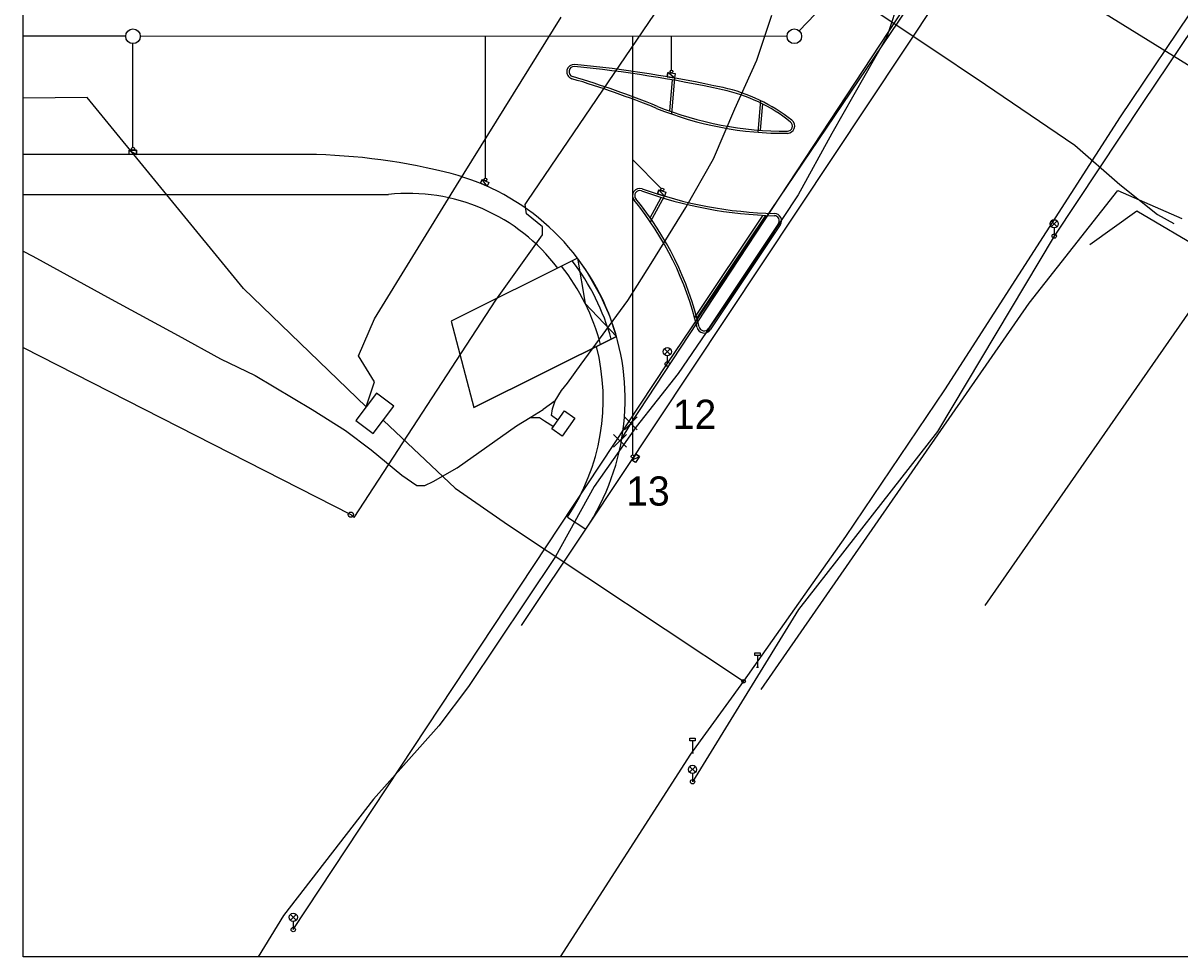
# Model space of a CAD drawing. Extents: x -263861 to -263441, y -1242367 to -1242070.
# Drawn here: x -263861.4 to -263782.2, y -1242367.2 to -1242303.2 of the extents above; entities that cross this region are included whole.
import ezdxf

# ---------------------------------------------------------------- set-up
doc = ezdxf.new("R2010")
doc.units = 0
for name, color, linetype in [('KFA_BODY', 7, 'Continuous'), ('KFA_JESTV_IS_DSP', 7, 'Continuous'), ('KFA_SITUACIA_DSP', 7, 'Continuous'), ('KFA_VO_prelozka_pri_vjazde_do KFA_TRASA', 7, 'Continuous'), ('RAM_NA_TLAC_A3_1-1000', 7, 'Continuous')]:
    doc.layers.add(name, color=color, linetype=linetype)

msp = doc.modelspace()

# ---------------------------------------------------------------- linework, layer by layer
at = {"layer": 'KFA_BODY'}
for p, q in [((-263820.235, -1242331.097), (-263819.351, -1242330.213)), ((-263819.351, -1242331.097), (-263820.235, -1242330.213)), ((-263819.793, -1242330.655), (-263819.793, -1242330.655)), ((-263820.978, -1242332.301), (-263820.094, -1242331.417)), ((-263820.094, -1242332.301), (-263820.978, -1242331.417)), ((-263820.536, -1242331.859), (-263820.536, -1242331.859))]:
    msp.add_line(p, q, dxfattribs=at)
at = {"layer": 'KFA_JESTV_IS_DSP'}
for p, q in [((-263771.766, -1242288.099), (-263786.259, -1242309.662)), ((-263817.295, -1242326.595), (-263792.966, -1242290.553)), ((-263806.91, -1242290.428), (-263775.785, -1242309.71)), ((-263775.662, -1242295.19), (-263784.703, -1242308.688)), ((-263826.85, -1242315.4), (-263815.315, -1242298.423)), ((-263809.14, -1242298.34), (-263799.44, -1242304.8)), ((-263801.33, -1242301.36), (-263802.26, -1242304.18)), ((-263831.753, -1242314.378), (-263824.576, -1242302.847)), ((-263811.16, -1242305.78), (-263810.13, -1242302.69)), ((-263802.26, -1242304.18), (-263806.02, -1242310.8)), ((-263799.44, -1242304.8), (-263795.49, -1242307.45)), ((-263812.66, -1242309.11), (-263811.16, -1242305.78)), ((-263795.49, -1242307.45), (-263789.36, -1242311.61)), ((-263857.064, -1242308.341), (-263861.443, -1242308.381)), ((-263846.335, -1242321.415), (-263857.064, -1242308.341)), ((-263814.12, -1242312.54), (-263812.66, -1242309.11)), ((-263784.703, -1242308.688), (-263790.778, -1242317.834)), ((-263786.259, -1242309.662), (-263798.305, -1242328.357)), ((-263806.02, -1242310.8), (-263808.33, -1242315.01)), ((-263789.36, -1242311.61), (-263786.29, -1242314.3)), ((-263816.02, -1242315.88), (-263814.12, -1242312.54)), ((-263837.368, -1242323.507), (-263831.753, -1242314.378)), ((-263792.5, -1242322.419), (-263786.416, -1242314.718)), ((-263786.416, -1242314.718), (-263782.039, -1242316.62)), ((-263786.29, -1242314.3), (-263783.7, -1242316.36)), ((-263827.03, -1242315.679), (-263826.85, -1242315.4)), ((-263827.03, -1242315.679), (-263826.85, -1242315.4)), ((-263808.33, -1242315.01), (-263812.71, -1242321.64)), ((-263826.939, -1242316.313), (-263827.03, -1242315.679)), ((-263826.939, -1242316.313), (-263827.03, -1242315.679)), ((-263825.841, -1242317.203), (-263826.939, -1242316.313)), ((-263825.841, -1242317.203), (-263826.939, -1242316.313)), ((-263818.4, -1242319.72), (-263816.02, -1242315.88)), ((-263788.344, -1242318.406), (-263785.115, -1242316.112)), ((-263785.115, -1242316.112), (-263778.688, -1242319.903)), ((-263783.7, -1242316.36), (-263782.58, -1242316.96)), ((-263790.977, -1242316.792), (-263790.579, -1242317.189)), ((-263790.579, -1242316.792), (-263790.977, -1242317.189)), ((-263829.05, -1242322.225), (-263825.851, -1242317.746)), ((-263825.851, -1242317.746), (-263825.841, -1242317.203)), ((-263825.851, -1242317.746), (-263825.841, -1242317.203)), ((-263790.778, -1242317.834), (-263798.769, -1242331.222)), ((-263790.778, -1242317.272), (-263790.778, -1242317.834)), ((-263861.443, -1242318.877), (-263860.78, -1242319.2)), ((-263860.78, -1242319.2), (-263855.41, -1242322.16)), ((-263778.588, -1242318.789), (-263795.542, -1242343.129)), ((-263820, -1242322.24), (-263818.4, -1242319.72)), ((-263837.937, -1242329.538), (-263846.335, -1242321.415)), ((-263812.71, -1242321.64), (-263816.56, -1242327.25)), ((-263855.41, -1242322.16), (-263850.82, -1242324.64)), ((-263838.758, -1242337.112), (-263829.05, -1242322.225)), ((-263823.2, -1242326.6), (-263820, -1242322.24)), ((-263810.862, -1242348.9), (-263792.5, -1242322.419)), ((-263838.469, -1242326.041), (-263837.368, -1242323.507)), ((-263850.82, -1242324.64), (-263847.92, -1242326.23)), ((-263861.443, -1242325.454), (-263838.982, -1242336.914)), ((-263817.494, -1242325.552), (-263817.096, -1242325.95)), ((-263817.096, -1242325.552), (-263817.494, -1242325.95)), ((-263847.92, -1242326.23), (-263845.54, -1242327.38)), ((-263842.931, -1242365.337), (-263817.295, -1242326.595)), ((-263837.363, -1242327.807), (-263838.469, -1242326.041)), ((-263824.13, -1242327.9), (-263823.2, -1242326.6)), ((-263817.295, -1242326.032), (-263817.295, -1242326.595)), ((-263845.54, -1242327.38), (-263841.63, -1242329.71)), ((-263816.56, -1242327.25), (-263819.43, -1242330.89)), ((-263837.937, -1242329.538), (-263837.363, -1242327.807)), ((-263824.55, -1242328.41), (-263824.13, -1242327.9)), ((-263837.233, -1242328.584), (-263838.648, -1242330.455)), ((-263836.032, -1242329.492), (-263837.233, -1242328.584)), ((-263824.97, -1242329.12), (-263824.55, -1242328.41)), ((-263798.305, -1242328.357), (-263805.079, -1242338.406)), ((-263841.63, -1242329.71), (-263839.35, -1242331.16)), ((-263837.446, -1242331.363), (-263836.032, -1242329.492)), ((-263826.7, -1242330.27), (-263825.81, -1242329.72)), ((-263824.97, -1242329.12), (-263825.81, -1242329.72)), ((-263825.23, -1242330.13), (-263825.17, -1242329.67)), ((-263825.21, -1242331.04), (-263824.35, -1242329.81)), ((-263825.17, -1242329.67), (-263824.97, -1242329.12)), ((-263824.35, -1242329.81), (-263823.64, -1242330.31)), ((-263838.648, -1242330.455), (-263837.446, -1242331.363)), ((-263836.754, -1242330.457), (-263831.833, -1242335.111)), ((-263827.64, -1242330.84), (-263826.7, -1242330.27)), ((-263826.7, -1242330.27), (-263826.06, -1242330.26)), ((-263826.06, -1242330.26), (-263825.71, -1242330.48)), ((-263825.71, -1242330.48), (-263825.1, -1242330.88)), ((-263824.79, -1242330.44), (-263825.23, -1242330.13)), ((-263823.64, -1242330.31), (-263824.5, -1242331.54)), ((-263839.35, -1242331.16), (-263837.6, -1242332.48)), ((-263831.7, -1242333.71), (-263827.64, -1242330.84)), ((-263824.5, -1242331.54), (-263825.21, -1242331.04)), ((-263819.43, -1242330.89), (-263822.31, -1242334.98)), ((-263798.769, -1242331.222), (-263808.3, -1242343.414)), ((-263837.6, -1242332.48), (-263835.49, -1242334.21)), ((-263833.34, -1242334.64), (-263831.7, -1242333.71)), ((-263835.49, -1242334.21), (-263834.45, -1242334.91)), ((-263833.91, -1242334.91), (-263833.34, -1242334.64)), ((-263834.45, -1242334.91), (-263833.91, -1242334.91)), ((-263831.833, -1242335.111), (-263828.189, -1242337.632)), ((-263822.31, -1242334.98), (-263824.95, -1242339.77)), ((-263838.982, -1242336.914), (-263838.758, -1242337.112)), ((-263828.189, -1242337.632), (-263812.07, -1242348.322)), ((-263805.079, -1242338.406), (-263812.07, -1242348.322)), ((-263824.95, -1242339.77), (-263830.93, -1242348.68)), ((-263808.3, -1242343.414), (-263815.565, -1242355.209)), ((-263811.305, -1242346.372), (-263810.93, -1242346.372)), ((-263811.305, -1242346.559), (-263811.305, -1242346.372)), ((-263810.93, -1242346.372), (-263810.93, -1242346.559)), ((-263810.93, -1242346.559), (-263811.305, -1242346.559)), ((-263811.118, -1242346.559), (-263811.118, -1242347.372)), ((-263811.18, -1242347.372), (-263811.055, -1242347.372)), ((-263830.93, -1242348.68), (-263832.95, -1242351.39)), ((-263812.07, -1242348.322), (-263815.715, -1242353.33)), ((-263832.95, -1242351.39), (-263837.44, -1242356.4)), ((-263815.76, -1242352.23), (-263815.385, -1242352.23)), ((-263815.76, -1242352.417), (-263815.76, -1242352.23)), ((-263815.385, -1242352.417), (-263815.76, -1242352.417)), ((-263815.572, -1242352.417), (-263815.572, -1242353.23)), ((-263815.385, -1242352.23), (-263815.385, -1242352.417)), ((-263815.715, -1242353.33), (-263824.645, -1242367.205)), ((-263815.635, -1242353.23), (-263815.51, -1242353.23)), ((-263815.764, -1242354.167), (-263815.366, -1242354.564)), ((-263815.366, -1242354.167), (-263815.764, -1242354.564)), ((-263815.565, -1242354.647), (-263815.565, -1242355.209)), ((-263837.44, -1242356.4), (-263843.59, -1242364.38)), ((-263843.59, -1242364.38), (-263845.324, -1242367.205)), ((-263843.13, -1242364.295), (-263842.732, -1242364.692)), ((-263842.732, -1242364.295), (-263843.13, -1242364.692)), ((-263842.931, -1242364.775), (-263842.931, -1242365.337))]:
    msp.add_line(p, q, dxfattribs=at)
for centre, radius in [((-263790.778, -1242316.99), 0.281), ((-263790.778, -1242317.834), 0.15), ((-263817.295, -1242325.751), 0.281), ((-263817.295, -1242326.595), 0.15), ((-263838.982, -1242336.914), 0.179), ((-263812.07, -1242348.322), 0.125), ((-263815.565, -1242354.365), 0.281), ((-263815.565, -1242355.209), 0.15), ((-263842.931, -1242364.493), 0.281), ((-263842.931, -1242365.337), 0.15)]:
    msp.add_circle(centre, radius, dxfattribs=at)
at = {"layer": 'KFA_SITUACIA_DSP'}
for p, q in [((-263822.88, -1242337.914), (-263734.49, -1242204.937)), ((-263780.353, -1242274.236), (-263808.248, -1242303.783)), ((-263854.415, -1242304.147), (-263861.443, -1242304.147)), ((-263809.091, -1242304.153), (-263853.415, -1242304.148)), ((-263829.755, -1242313.856), (-263829.755, -1242304.151)), ((-263819.667, -1242332.824), (-263819.667, -1242304.147)), ((-263817.005, -1242306.465), (-263817.005, -1242304.152)), ((-263853.915, -1242311.749), (-263853.915, -1242304.647)), ((-263817.296, -1242306.914), (-263817.252, -1242306.627)), ((-263817.252, -1242306.627), (-263817.296, -1242306.914)), ((-263817.252, -1242306.627), (-263816.757, -1242306.703)), ((-263816.802, -1242306.99), (-263817.252, -1242306.627)), ((-263816.802, -1242306.99), (-263817.252, -1242306.627)), ((-263816.757, -1242306.703), (-263816.802, -1242306.99)), ((-263816.802, -1242306.99), (-263817.296, -1242306.914)), ((-263817.296, -1242306.914), (-263816.802, -1242306.99)), ((-263816.964, -1242307.132), (-263817.145, -1242309.262)), ((-263816.803, -1242307.008), (-263817.012, -1242309.468)), ((-263810.912, -1242308.547), (-263811.097, -1242310.721)), ((-263810.781, -1242308.779), (-263810.935, -1242310.583)), ((-263861.443, -1242312.232), (-263857.327, -1242312.232)), ((-263842.601, -1242312.24), (-263861.443, -1242312.238)), ((-263854.165, -1242311.949), (-263853.665, -1242311.949)), ((-263854.165, -1242312.239), (-263854.165, -1242311.949)), ((-263854.165, -1242311.949), (-263853.665, -1242312.239)), ((-263854.165, -1242311.949), (-263853.665, -1242312.239)), ((-263853.665, -1242311.949), (-263854.165, -1242311.949)), ((-263853.665, -1242312.239), (-263854.165, -1242312.239)), ((-263853.665, -1242311.949), (-263853.665, -1242312.239)), ((-263853.665, -1242312.239), (-263853.665, -1242311.949)), ((-263817.708, -1242314.574), (-263819.667, -1242312.615)), ((-263830.101, -1242314.219), (-263829.983, -1242313.954)), ((-263829.983, -1242313.954), (-263830.101, -1242314.219)), ((-263829.983, -1242313.954), (-263829.527, -1242314.158)), ((-263829.645, -1242314.423), (-263829.983, -1242313.954)), ((-263829.645, -1242314.423), (-263829.983, -1242313.954)), ((-263829.645, -1242314.423), (-263830.101, -1242314.219)), ((-263830.101, -1242314.219), (-263829.645, -1242314.423)), ((-263829.527, -1242314.158), (-263829.645, -1242314.423)), ((-263817.966, -1242314.94), (-263817.874, -1242314.665)), ((-263817.874, -1242314.665), (-263817.966, -1242314.94)), ((-263817.874, -1242314.665), (-263817.4, -1242314.824)), ((-263817.492, -1242315.099), (-263817.874, -1242314.665)), ((-263817.492, -1242315.099), (-263817.874, -1242314.665)), ((-263861.443, -1242314.982), (-263836.403, -1242314.982)), ((-263818.469, -1242316.58), (-263817.711, -1242315.183)), ((-263818.453, -1242316.866), (-263817.491, -1242315.093)), ((-263817.492, -1242315.099), (-263817.966, -1242314.94)), ((-263817.966, -1242314.94), (-263817.492, -1242315.099)), ((-263817.4, -1242314.824), (-263817.492, -1242315.099)), ((-263810.751, -1242316.405), (-263815.43, -1242323.41)), ((-263810.576, -1242316.414), (-263815.268, -1242323.437)), ((-263809.676, -1242316.98), (-263814.48, -1242324.171)), ((-263809.551, -1242317.064), (-263814.356, -1242324.254)), ((-263823.444, -1242319.346), (-263832.112, -1242323.652)), ((-263813.542, -1242320.69), (-263813.542, -1242320.69)), ((-263813.542, -1242320.69), (-263813.542, -1242320.69)), ((-263832.112, -1242323.652), (-263830.544, -1242329.573)), ((-263820.775, -1242324.719), (-263830.544, -1242329.573)), ((-263819.723, -1242333.187), (-263819.444, -1242332.772)), ((-263819.723, -1242333.187), (-263819.203, -1242332.933)), ((-263819.203, -1242332.933), (-263819.482, -1242333.349)), ((-263819.444, -1242332.772), (-263819.203, -1242332.933)), ((-263819.482, -1242333.349), (-263819.723, -1242333.187)), ((-263824.127, -1242337.081), (-263822.88, -1242337.914)), ((-263827.28, -1242344.5), (-263822.88, -1242337.914))]:
    msp.add_line(p, q, dxfattribs=at)
for points in [[(-263832.112, -1242323.652), (-263830.544, -1242329.573), (-263820.775, -1242324.719), (-263821.24, -1242323.31), (-263821.84, -1242321.938), (-263822.869, -1242320.154), (-263823.444, -1242319.346), (-263832.112, -1242323.652)], [(-263823.444, -1242319.346), (-263822.93, -1242322.44), (-263820.775, -1242324.719)]]:
    msp.add_lwpolyline(points, dxfattribs=at)
msp.add_lwpolyline([(-263819.723, -1242333.187), (-263819.203, -1242332.933), (-263819.444, -1242332.772)], close=True, dxfattribs=at)
for centre, radius in [((-263853.915, -1242304.147), 0.5), ((-263808.591, -1242304.147), 0.5), ((-263817.005, -1242306.565), 0.1), ((-263853.915, -1242311.849), 0.1), ((-263829.755, -1242313.956), 0.1), ((-263817.637, -1242314.644), 0.1), ((-263819.667, -1242332.924), 0.1)]:
    msp.add_circle(centre, radius, dxfattribs=at)
for centre, radius, start, end in [((-263823.686, -1242306.574), 0.5, 84.50312, 253.37264), ((-263832, -1242392.966), 87.291, 77.74517, 84.50312), ((-263823.686, -1242306.574), 0.35, 84.50312, 253.37264), ((-263832, -1242392.966), 87.141, 77.74517, 84.50312), ((-263842.678, -1242370.168), 65.869, 68.01969, 73.37264), ((-263842.678, -1242370.168), 66.019, 68.01969, 73.37264), ((-263815.913, -1242318.902), 11.5, 51.49122, 77.74517), ((-263815.913, -1242318.902), 11.35, 51.49122, 77.74517), ((-263809.228, -1242287.295), 23.5, 248.01969, 270.4085), ((-263809.228, -1242287.295), 23.35, 248.01969, 270.4085), ((-263809.064, -1242310.295), 0.35, 270.4085, 51.49122), ((-263809.064, -1242310.295), 0.5, 270.4085, 51.49122), ((-263842.427, -1242353.351), 41.111, 76.13622, 90.24149), ((-263836.184, -1242329.025), 16, 326.2529, 76.96946), ((-263819.181, -1242315.066), 0.5, 70.28283, 219.38571), ((-263819.181, -1242315.066), 0.35, 70.28283, 219.38571), ((-263809.228, -1242287.295), 29.15, 250.28283, 268.56407), ((-263809.228, -1242287.295), 29, 250.28283, 268.56407), ((-263835.045, -1242327.715), 12.805, 36.92053, 96.08735), ((-263836.184, -1242329.025), 21.5, 13.26701, 39.38571), ((-263836.184, -1242329.025), 21.65, 13.26701, 39.38571), ((-263809.967, -1242316.786), 0.5, 326.2529, 88.56407), ((-263809.967, -1242316.786), 0.35, 326.2529, 88.56407), ((-263836.184, -1242329.025), 15.6, 15.3332, 37.50818), ((-263836.184, -1242329.025), 14.8, 14.72564, 38.11574), ((-263836.184, -1242329.025), 21.65, 13.26701, 14.95961), ((-263814.771, -1242323.977), 0.5, 193.26701, 326.2529), ((-263814.771, -1242323.977), 0.35, 193.26701, 326.2529), ((-263836.228, -1242329.021), 14.539, 326.33444, 14.41665)]:
    msp.add_arc(centre, radius, start, end, dxfattribs=at)
at = {"layer": 'KFA_VO_prelozka_pri_vjazde_do KFA_TRASA'}
msp.add_lwpolyline([(-263678.348, -1242101.421), (-263696.564, -1242141.184), (-263711.214, -1242160.531), (-263718.885, -1242173.716), (-263725.972, -1242184.27), (-263742.987, -1242211.896), (-263755.733, -1242230.932), (-263756.364, -1242233.146), (-263759.746, -1242241.517), (-263769.698, -1242254.926), (-263792.513, -1242289.186), (-263819.793, -1242330.655), (-263820.536, -1242331.859)], dxfattribs=at)
at = {"layer": 'RAM_NA_TLAC_A3_1-1000'}
msp.add_lwpolyline([(-263861.443, -1242070.205), (-263441.443, -1242070.205), (-263441.443, -1242367.205), (-263861.443, -1242367.205)], close=True, dxfattribs=at)

# ---------------------------------------------------------------- texts
at = {"layer": 'KFA_BODY'}
for s, p in [('12', (-263816.914, -1242331.041)), ('13', (-263820.107, -1242336.296))]:
    msp.add_text(s, height=2, dxfattribs=at).set_placement(p)

doc.saveas('drawing.dxf')
